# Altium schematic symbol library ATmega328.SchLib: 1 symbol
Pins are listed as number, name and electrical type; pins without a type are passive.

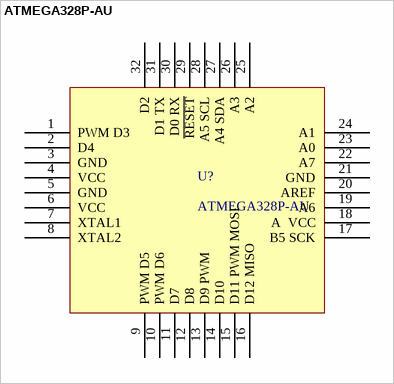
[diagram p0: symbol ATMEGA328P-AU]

## ATMEGA328P-AU
designator U?
Microchip Technology ATMEGA328P-AU, 8bit AVR Microcontroller, 20MHz, 32 kB Flash, 32-Pin TQFP
footprint TQFP80P900X900X120-32N (TQFP, 32-Leads, Body 7.00x7.00mm, Pitch 0.80mm, IPC Medium Density)
pins: 1 PWM D3, 2 D4, 3 GND, 4 VCC, 5 GND, 6 VCC, 7 XTAL1, 8 XTAL2, 9 PWM D5, 10 PWM D6, 11 D7, 12 D8, 13 D9 PWM, 14 D10, 15 D11 PWM MOSI, 16 D12 MISO, 17 B5 SCK, 18 A  VCC, 19 A6, 20 AREF, 21 GND, 22 A7, 23 A0, 24 A1, 25 A2, 26 A3, 27 A4 SDA, 28 A5 SCL, 29 ~{RESET}, 30 D0 RX, 31 D1 TX, 32 D2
